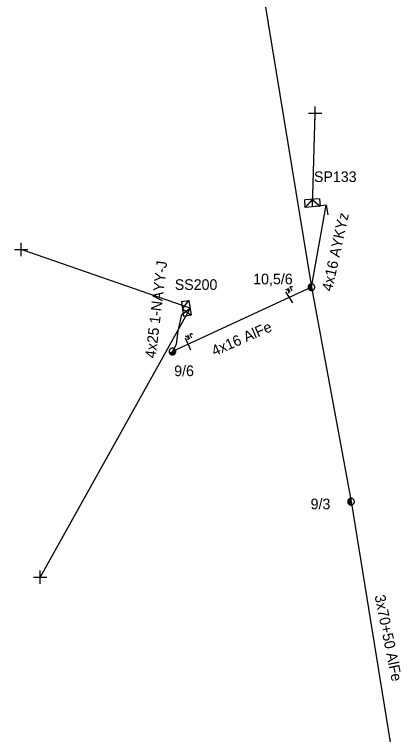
# Model space of a CAD drawing. Extents: x -717562 to -713845, y -1151196 to -1143903.
# Drawn here: x -716985.1 to -716948.3, y -1145266.3 to -1145198.5 of the extents above; entities that cross this region are included whole.
import ezdxf

# ---------------------------------------------------------------- set-up
doc = ezdxf.new("R2010")
doc.units = 0
for name, color, linetype in [('Vrstva 1', 7, 'Continuous'), ('Vrstva 12', 7, 'Continuous'), ('Vrstva 13', 7, 'Continuous'), ('Vrstva 15', 7, 'Continuous'), ('Vrstva 18', 7, 'Continuous'), ('Vrstva 2', 7, 'Continuous'), ('Vrstva 31', 7, 'Continuous'), ('Vrstva 33', 7, 'Continuous'), ('Vrstva 34', 7, 'Continuous'), ('Vrstva 52', 7, 'Continuous'), ('Vrstva 54', 7, 'Continuous'), ('Vrstva 55', 7, 'Continuous'), ('Vrstva 59', 7, 'Continuous'), ('Vrstva 9', 7, 'Continuous')]:
    doc.layers.add(name, color=color, linetype=linetype)

# ---------------------------------------------------------------- blocks, each defined once
blk = doc.blocks.new('NN440')
at = {"layer": 'Vrstva 2'}
for points in [[(0.63, 0), (0.63, 0.06), (0.62, 0.13), (0.6, 0.19), (0.58, 0.25), (0.55, 0.31), (0.51, 0.37), (0.47, 0.42), (0.42, 0.46), (0.37, 0.51), (0.32, 0.54), (0.26, 0.57), (0.2, 0.59), (0.13, 0.61), (0.07, 0.62), (0, 0.63), (-0.06, 0.62), (-0.13, 0.61), (-0.19, 0.59), (-0.26, 0.57), (-0.31, 0.54), (-0.37, 0.51), (-0.42, 0.46), (-0.47, 0.42), (-0.51, 0.37), (-0.54, 0.31), (-0.57, 0.25), (-0.6, 0.19), (-0.62, 0.13), (-0.63, 0.06), (-0.63, 0), (-0.63, -0.07), (-0.62, -0.14), (-0.6, -0.2), (-0.57, -0.26), (-0.54, -0.32), (-0.51, -0.37), (-0.47, -0.43), (-0.42, -0.47), (-0.37, -0.51), (-0.31, -0.55), (-0.26, -0.58), (-0.19, -0.6), (-0.13, -0.62), (-0.06, -0.63), (0, -0.63), (0.07, -0.63), (0.13, -0.62), (0.2, -0.6), (0.26, -0.58), (0.32, -0.55), (0.37, -0.51), (0.42, -0.47), (0.47, -0.43), (0.51, -0.37), (0.55, -0.32), (0.58, -0.26), (0.6, -0.2), (0.62, -0.14), (0.63, -0.07), (0.63, 0)], [(-0.63, 0), (0.63, 0)], [(-0.6, -0.18), (0.57, -0.18)], [(-0.51, -0.32), (0.5, -0.32)], [(-0.37, -0.47), (0.35, -0.47)]]:
    blk.add_lwpolyline(points, dxfattribs=at)
blk = doc.blocks.new('NN840')
at = {"layer": 'Vrstva 15'}
for points in [[(0.003, 0.619), (0.003, -0.631)], [(-0.745, -0.71), (-0.745, -0.66)], [(-0.538, -0.385), (-0.538, -0.71)], [(-0.332, -0.385), (-0.332, -0.798)], [(-0.332, -0.641), (-0.125, -0.385)], [(-0.263, -0.557), (-0.091, -0.798)], [(-0.73, -0.764), (-0.745, -0.71)], [(-0.657, -0.798), (-0.73, -0.764)], [(-0.627, -0.798), (-0.657, -0.798)], [(-0.558, -0.764), (-0.627, -0.798)], [(-0.538, -0.71), (-0.558, -0.764)]]:
    blk.add_lwpolyline(points, dxfattribs=at)
blk = doc.blocks.new('NN800')
at = {"layer": 'Vrstva 1'}
for points in [[(-0.442, 0.442), (0.442, -0.442)], [(-0.442, -0.442), (0.442, 0.442)]]:
    blk.add_lwpolyline(points, dxfattribs=at)
blk = doc.blocks.new('NN630')
at = {"layer": 'Vrstva 9'}
for points in [[(-0.003, -0.7), (-0.703, 0)], [(-0.703, -0.7), (-0.703, 0), (0.697, 0), (0.697, -0.7)], [(-0.003, -0.7), (0.697, 0)], [(-0.703, -0.7), (0.697, -0.7)]]:
    blk.add_lwpolyline(points, dxfattribs=at)
blk = doc.blocks.new('NN510')
at = {"layer": 'Vrstva 2'}
blk.add_lwpolyline([(0.001, 0.002), (0.001, 0.939)], dxfattribs=at)

msp = doc.modelspace()

# ---------------------------------------------------------------- linework, layer by layer
at = {"layer": 'Vrstva 1'}
for points in [[(-716965.196, -1145134.329), (-716967.336, -1145163.569), (-716962.356, -1145192.449), (-716957.136, -1145224.189)], [(-716957.136, -1145224.189), (-716970.239, -1145230.25)], [(-716957.137, -1145224.189), (-716953.406, -1145244.389), (-716948.267, -1145275.949)]]:
    msp.add_lwpolyline(points, dxfattribs=at)
at = {"layer": 'Vrstva 52'}
msp.add_lwpolyline([(-716970.239, -1145230.25), (-716969.859, -1145229.57), (-716969.709, -1145228.32), (-716969.339, -1145226.75), (-716968.579, -1145226.15)], dxfattribs=at)
at = {"layer": 'Vrstva 54'}
msp.add_lwpolyline([(-716957.136, -1145224.189), (-716955.746, -1145216.459), (-716957.026, -1145216.619)], dxfattribs=at)
at = {"layer": 'Vrstva 59'}
for points in [[(-716957.026, -1145216.619), (-716956.786, -1145207.809)], [(-716968.579, -1145226.15), (-716984.5, -1145220.63)], [(-716968.579, -1145226.15), (-716982.69, -1145251.5)]]:
    msp.add_lwpolyline(points, dxfattribs=at)

# ---------------------------------------------------------------- block references
at = {"layer": 'Vrstva 13', "rotation": -171.5401778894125}
msp.add_blockref('NN510', (-716955.746, -1145216.459), dxfattribs=at)
at = {"layer": 'Vrstva 13', "xscale": 0.5}
for p, yscale, rotation in [((-716957.136, -1145224.189), 0.49999999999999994, -77.42632500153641), ((-716970.239, -1145230.25), 0.5, 24.82293372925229), ((-716953.406, -1145244.389), 0.5000000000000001, -78.61901116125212)]:
    msp.add_blockref('NN440', p, dxfattribs=dict(at, yscale=yscale, rotation=rotation))
at = {"layer": 'Vrstva 18'}
for p, rotation in [((-716959.206, -1145225.145), -147.98239158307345), ((-716968.747, -1145229.559), -155.1770662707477)]:
    msp.add_blockref('NN840', p, dxfattribs=dict(at, rotation=rotation))
at = {"layer": 'Vrstva 31'}
for p, rotation in [((-716957.026, -1145216.619), -175.87838485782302), ((-716968.579, -1145226.15), -82.12606183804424)]:
    msp.add_blockref('NN630', p, dxfattribs=dict(at, rotation=rotation))
at = {"layer": 'Vrstva 34'}
for p, rotation in [((-716956.786, -1145207.809), 44.99999995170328), ((-716984.5, -1145220.63), 45), ((-716982.69, -1145251.5), 44.99999995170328)]:
    msp.add_blockref('NN800', p, dxfattribs=dict(at, rotation=rotation))

# ---------------------------------------------------------------- texts
at = {"layer": 'Vrstva 12'}
for s, p in [('10,5/6', (-716962.625, -1145223.919)), ('9/6', (-716970.07, -1145232.568)), ('9/3', (-716957.215, -1145245.107))]:
    msp.add_text(s, height=1, dxfattribs=at).set_placement(p)
at = {"layer": 'Vrstva 2'}
for s, rotation, p in [('4x16 AlFe', 23.544, (-716966.283, -1145230.695)), ('3x70+50 AlFe', 281.381, (-716951.193, -1145253.26))]:
    msp.add_text(s, height=1, rotation=rotation, dxfattribs=at).set_placement(p)
at = {"layer": 'Vrstva 33'}
for s, p in [('SP133', (-716956.898, -1145214.282)), ('SS200', (-716970.016, -1145224.443))]:
    msp.add_text(s, height=1, dxfattribs=at).set_placement(p)
at = {"layer": 'Vrstva 54'}
msp.add_text('4x25 1-NAYY-J', height=1, rotation=83.157, dxfattribs=at).set_placement((-716971.822, -1145230.926))
at = {"layer": 'Vrstva 55'}
msp.add_text('4x16 AYKYz', height=1, rotation=77.689, dxfattribs=at).set_placement((-716955.2, -1145224.636))

doc.saveas('drawing.dxf')
